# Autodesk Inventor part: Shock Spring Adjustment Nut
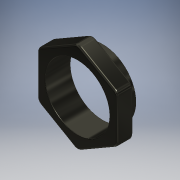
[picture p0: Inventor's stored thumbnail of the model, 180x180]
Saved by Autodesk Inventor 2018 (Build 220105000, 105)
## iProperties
Shininess: 50.0
Compacted: True
Length Units: 11272
Angle Units: 11279
Time Units: 11290
Mass Units: 11286
Length Display Precision: 4
Angle Display Precision: 2
Company: Autodesk
Created: 2000-03
Part Number: Shock Spring Adjustment Nut
Project: Inventor Samples
User Status: IN PROGRESS
Document SubType Name: Modeling
Designer: Autodesk, Inc.
Density: 1.13 g/cm^3
Mass: 0.350545 g
Surface Area: 6.09851 cm^2
Volume: 0.310217 cm^3
Material: Nylon-6/6
Appearance: Gunmetal
Density: 0.0
Volumn: 0.0
Area: 0.0
PropertySet Name: Model Information
Control State: 0
Master: False
Checked Out: False
Author: Autodesk, Inc.
Revision Number: A
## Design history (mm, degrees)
node "Extrusion1" dims "d1" = 1.905, "d2" = 0
  sketch "Sketch2"
    geometry: C1 r 6.668 at (-5.692, -2.081)
    constraints: 1 centre point
    dimensions: "d0" = 13.335 diameter of C1
node "Extrusion2" dims "d4" = 3.175, "d5" = 0
  sketch "Sketch3"
    geometry: L1 (-7.938, -4.583)-(-7.938, 4.583); L2 (-7.938, 4.583)-(0, 9.165); L3 (0, 9.165)-(7.938, 4.583); L4 (7.938, 4.583)-(7.938, -4.583); L5 (7.938, -4.583)-(0, -9.165); L6 (0, -9.165)-(-7.938, -4.583); C1 r 7.938 at (0, 0); C2 r 6.668 at (0, 0) reference
    constraints: 12 end point, 6 tangent, 4 equal length, 1 centre point, 1 concentric, 1 parallel, 1 vertical
    dimensions: "d3" = 15.875 diameter of C1
node "Extrusion3" dims "d7" = 3.175, "d8" = 0
  sketch "Sketch4"
    geometry: C1 r 6.35 at (0, 0); C2 r 6.668 at (0, 0) reference
    constraints: 1 centre point, 1 coincident
    dimensions: "d6" = 12.7 diameter of C1
node "Fillet1" dims "d9" = 1.27
node "Fillet2" dims "d10" = 0.381, "d11" = 0.127
body "Solid1"
